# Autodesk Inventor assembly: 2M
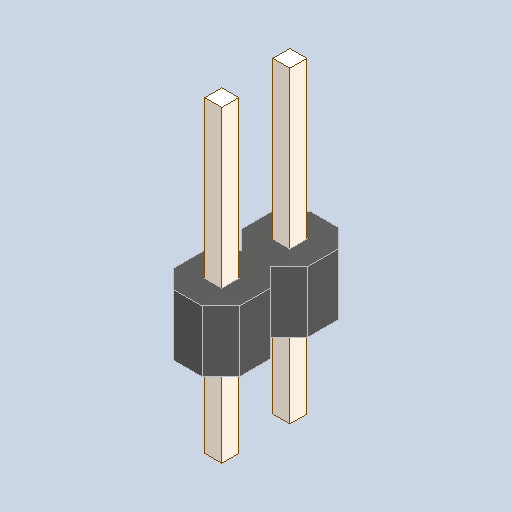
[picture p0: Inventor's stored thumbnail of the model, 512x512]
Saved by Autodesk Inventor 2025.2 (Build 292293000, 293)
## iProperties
Created: 2025-04
Part Number: 2M
Description: PART--DESC
Document SubType Name: Assembly
Designer: BennF
Author: BennF
Revision Number: NONE
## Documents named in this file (3)
- C:\Users\BennF\Nextcloud\Benutzer\CNC JarBeRi\existing parts\Electronics\RepRap A4988 Shied (USE WITHOUT ARDUINO)\reprap-a4988-1.snapshot.1\RepRap\RepRap\2M.iam
- C:\Users\BennF\Nextcloud\Benutzer\CNC JarBeRi\existing parts\Electronics\RepRap A4988 Shied (USE WITHOUT ARDUINO)\reprap-a4988-1.snapshot.1\RepRap\RepRap\2M Geometry.ipt
- C:\Users\BennF\Nextcloud\Benutzer\CNC JarBeRi\existing parts\Electronics\RepRap A4988 Shied (USE WITHOUT ARDUINO)\reprap-a4988-1.snapshot.1\RepRap\RepRap\Pin12.ipt
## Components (2 placed, 2 different names)
1. 2M Geometry
2. Pin12
